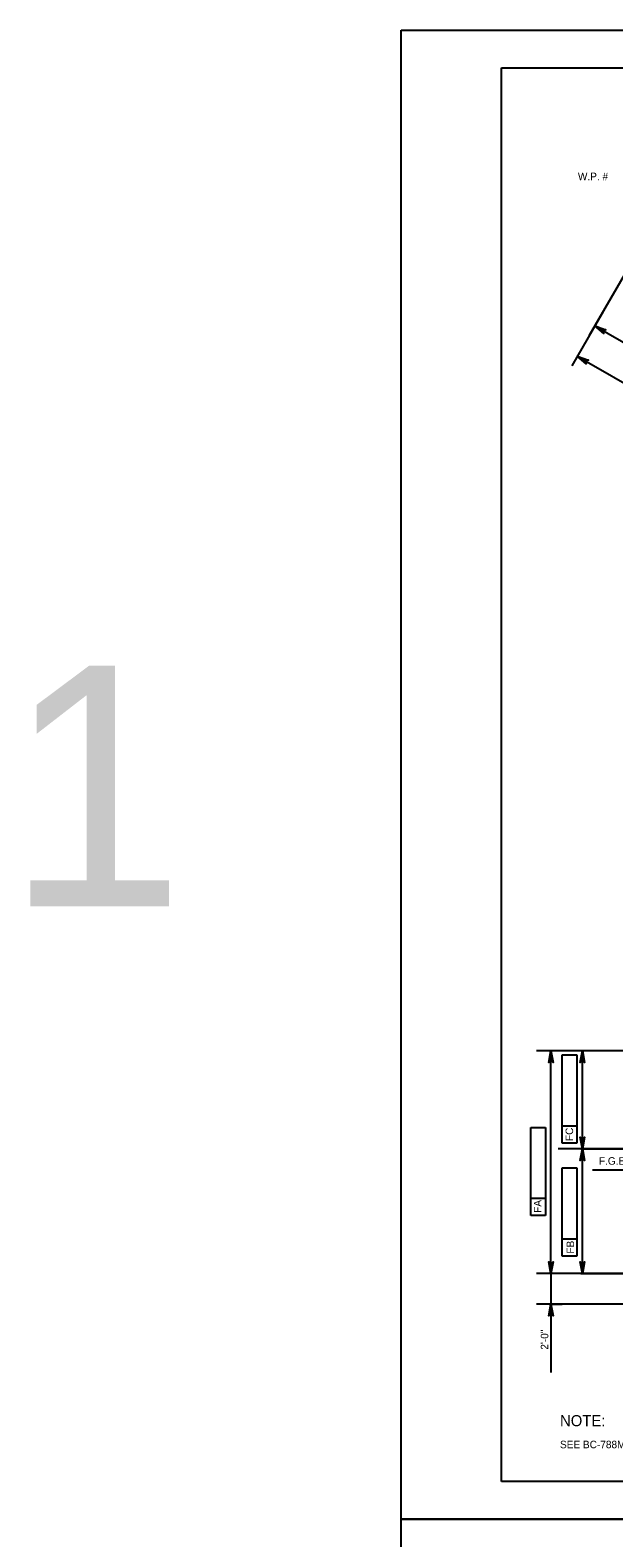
# Model space of a CAD drawing. Extents: x 638255 to 640306, y 296059 to 298435.
# Drawn here: x 638288 to 638520, y 297834 to 298435 of the extents above; entities that cross this region are included whole.
import ezdxf

# ---------------------------------------------------------------- set-up
doc = ezdxf.new("R2010")
doc.units = 0
for name, color, linetype in [('2', 7, 'Continuous'), ('4', 7, 'Continuous'), ('Level 3', 7, 'Continuous'), ('PLT-BNDY', 7, 'Continuous')]:
    doc.layers.add(name, color=color, linetype=linetype)

msp = doc.modelspace()

# ---------------------------------------------------------------- linework, layer by layer
at = {"layer": '2'}
for p, q in [((638475.46, 297856.46), (638475.46, 298420.46)), ((638475.46, 298420.46), (639261.46, 298420.46)), ((639261.46, 297856.46), (638475.46, 297856.46))]:
    msp.add_line(p, q, dxfattribs=at)
at = {"layer": 'Level 3'}
for p, q in [((638538.04, 298361.51), (638510.43, 298313.67)), ((638515.96, 298323.25), (638503.45, 298301.6)), ((638512.64, 298317.5), (638587.08, 298274.52)), ((638505.66, 298305.42), (638582.47, 298261.08)), ((638643.25, 298028.22), (638489.4, 298028.22)), ((638495.51, 298028.23), (638490.75, 298028.23)), ((638502.7, 298028.23), (638490.75, 298028.23)), ((638495.17, 297939.44), (638495.17, 298028.23)), ((638499.6, 298026.61), (638505.49, 298026.61)), ((638499.6, 297998.21), (638499.6, 298026.61)), ((638542.74, 298028.23), (638503.27, 298028.23)), ((638505.49, 298026.61), (638505.49, 297991.38)), ((638507.69, 297989.17), (638507.69, 298028.23)), ((638487.12, 297997.73), (638493.01, 297997.73)), ((638487.12, 297969.33), (638487.12, 297997.73)), ((638493.01, 297997.73), (638493.01, 297962.5)), ((638499.6, 297991.38), (638499.6, 297998.21)), ((638505.49, 297998.21), (638499.6, 297998.21)), ((638577.26, 297989.17), (638498.1, 297989.17)), ((638505.49, 297991.38), (638499.6, 297991.38)), ((638542.74, 297989.17), (638503.27, 297989.17)), ((638549.14, 297989.17), (638503.27, 297989.17)), ((638507.11, 297989.17), (638542.57, 297989.17)), ((638507.69, 297939.44), (638507.69, 297989.17)), ((638499.6, 297981.56), (638505.49, 297981.56)), ((638499.6, 297953.16), (638499.6, 297981.56)), ((638505.49, 297981.56), (638505.49, 297946.33)), ((638572.66, 297980.61), (638511.76, 297980.61)), ((638487.12, 297962.5), (638487.12, 297969.33)), ((638493.01, 297969.33), (638487.12, 297969.33)), ((638493.01, 297962.5), (638487.12, 297962.5)), ((638499.6, 297946.33), (638499.6, 297953.16)), ((638505.49, 297953.16), (638499.6, 297953.16)), ((638505.49, 297946.33), (638499.6, 297946.33)), ((638577.26, 297939.44), (638489.4, 297939.44)), ((638495.51, 297939.44), (638490.75, 297939.44)), ((638502.7, 297939.44), (638490.75, 297939.44)), ((638495.17, 297939.44), (638495.17, 297927.16)), ((638549.14, 297939.44), (638503.27, 297939.44)), ((638507.11, 297939.44), (638542.57, 297939.44)), ((638577.26, 297927.16), (638489.4, 297927.16)), ((638494.57, 297927.16), (638499.59, 297927.16)), ((638495.17, 297927.16), (638495.17, 297899.86))]:
    msp.add_line(p, q, dxfattribs=at)
for points in [[(638515.43, 298316.45), (638514.94, 298315.6), (638512.64, 298317.5)], [(638508.46, 298304.38), (638507.97, 298303.52), (638505.66, 298305.42)], [(638494.68, 298025.28), (638495.66, 298025.28), (638495.17, 298028.23)], [(638507.2, 298025.28), (638508.19, 298025.28), (638507.69, 298028.23)], [(638507.2, 297992.12), (638508.19, 297992.12), (638507.69, 297989.17)], [(638507.2, 297986.23), (638508.19, 297986.23), (638507.69, 297989.17)], [(638494.68, 297942.39), (638495.66, 297942.39), (638495.17, 297939.44)], [(638507.2, 297942.39), (638508.19, 297942.39), (638507.69, 297939.44)], [(638494.68, 297924.22), (638495.66, 297924.22), (638495.17, 297927.16)]]:
    msp.add_lwpolyline(points, close=True, dxfattribs=at)
for points in [[(638512.64, 298317.5), (638517.1, 298315.93), (638516.67, 298315.89), (638516.35, 298315.71), (638516.15, 298315.47), (638516.04, 298315.17), (638516.04, 298314.81), (638516.23, 298314.42), (638512.64, 298317.5), (638516.04, 298314.81), (638516.04, 298315.17), (638512.64, 298317.5), (638516.15, 298315.47), (638516.35, 298315.71), (638512.64, 298317.5), (638516.67, 298315.89)], [(638505.66, 298305.42), (638510.13, 298303.85), (638509.69, 298303.82), (638509.38, 298303.64), (638509.18, 298303.4), (638509.07, 298303.1), (638509.07, 298302.74), (638509.26, 298302.34), (638505.66, 298305.42), (638509.07, 298302.74), (638509.07, 298303.1), (638505.66, 298305.42), (638509.18, 298303.4), (638509.38, 298303.64), (638505.66, 298305.42), (638509.69, 298303.82)], [(638495.17, 298028.23), (638496.04, 298023.57), (638495.79, 298023.93), (638495.48, 298024.12), (638495.17, 298024.17), (638494.86, 298024.12), (638494.55, 298023.93), (638494.3, 298023.57), (638495.17, 298028.23), (638494.55, 298023.93), (638494.86, 298024.12), (638495.17, 298028.23), (638495.17, 298024.17), (638495.48, 298024.12), (638495.17, 298028.23), (638495.79, 298023.93)], [(638507.69, 298028.23), (638508.57, 298023.57), (638508.32, 298023.93), (638508.01, 298024.12), (638507.69, 298024.17), (638507.38, 298024.12), (638507.07, 298023.93), (638506.82, 298023.57), (638507.69, 298028.23), (638507.07, 298023.93), (638507.38, 298024.12), (638507.69, 298028.23), (638507.69, 298024.17), (638508.01, 298024.12), (638507.69, 298028.23), (638508.32, 298023.93)], [(638507.69, 297989.17), (638506.82, 297993.83), (638507.07, 297993.47), (638507.38, 297993.28), (638507.69, 297993.23), (638508.01, 297993.28), (638508.32, 297993.47), (638508.57, 297993.83), (638507.69, 297989.17), (638508.32, 297993.47), (638508.01, 297993.28), (638507.69, 297989.17), (638507.69, 297993.23), (638507.38, 297993.28), (638507.69, 297989.17), (638507.07, 297993.47)], [(638507.69, 297989.17), (638508.57, 297984.52), (638508.32, 297984.88), (638508.01, 297985.07), (638507.69, 297985.12), (638507.38, 297985.07), (638507.07, 297984.88), (638506.82, 297984.52), (638507.69, 297989.17), (638507.07, 297984.88), (638507.38, 297985.07), (638507.69, 297989.17), (638507.69, 297985.12), (638508.01, 297985.07), (638507.69, 297989.17), (638508.32, 297984.88)], [(638495.17, 297939.44), (638494.3, 297944.09), (638494.55, 297943.74), (638494.86, 297943.55), (638495.17, 297943.5), (638495.48, 297943.55), (638495.79, 297943.74), (638496.04, 297944.09), (638495.17, 297939.44), (638495.79, 297943.74), (638495.48, 297943.55), (638495.17, 297939.44), (638495.17, 297943.5), (638494.86, 297943.55), (638495.17, 297939.44), (638494.55, 297943.74)], [(638507.69, 297939.44), (638506.82, 297944.09), (638507.07, 297943.74), (638507.38, 297943.55), (638507.69, 297943.5), (638508.01, 297943.55), (638508.32, 297943.74), (638508.57, 297944.09), (638507.69, 297939.44), (638508.32, 297943.74), (638508.01, 297943.55), (638507.69, 297939.44), (638507.69, 297943.5), (638507.38, 297943.55), (638507.69, 297939.44), (638507.07, 297943.74)], [(638495.17, 297927.16), (638496.04, 297922.51), (638495.79, 297922.87), (638495.48, 297923.05), (638495.17, 297923.11), (638494.86, 297923.05), (638494.55, 297922.87), (638494.3, 297922.51), (638495.17, 297927.16), (638494.55, 297922.87), (638494.86, 297923.05), (638495.17, 297927.16), (638495.17, 297923.11), (638495.48, 297923.05), (638495.17, 297927.16), (638495.79, 297922.87)]]:
    msp.add_lwpolyline(points, dxfattribs=at)
at = {"layer": 'PLT-BNDY'}
for points in [[(638435.46, 298435.46), (639276.46, 298435.46), (639276.46, 297841.46), (638435.46, 297841.46)], [(638435.46, 297841.46), (639276.46, 297841.46), (639276.46, 297247.46), (638435.46, 297247.46)]]:
    msp.add_lwpolyline(points, close=True, dxfattribs=at)

# ---------------------------------------------------------------- texts
at = {"layer": '2'}
msp.add_text('SEE BC-788M FOR ABUTMENT AND WINGWALL WATERPROOFING DETAIL.', height=3.0001, dxfattribs=at).set_placement((638498.79, 297869.7))
at = {"layer": '4'}
for s, height, p in [('1', 96, (638277.87, 298085.88)), ('NOTE:', 4.429, (638498.79, 297878.49))]:
    msp.add_text(s, height=height, dxfattribs=at).set_placement(p)
at = {"layer": 'Level 3'}
for s, p in [('W.P. # ', (638505.92, 298375.6)), ('F.G.E.', (638514.29, 297982.82))]:
    msp.add_text(s, height=3, dxfattribs=at).set_placement(p)
for s, p in [('FC', (638504.01, 297992.27)), ('FA', (638491.36, 297963.62)), ('FB', (638504.4, 297947.35)), ('2\'-0"', (638494.12, 297909.03))]:
    msp.add_text(s, height=3, rotation=90, dxfattribs=at).set_placement(p)

doc.saveas('drawing.dxf')
